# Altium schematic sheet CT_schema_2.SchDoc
size 276 x 169 mm
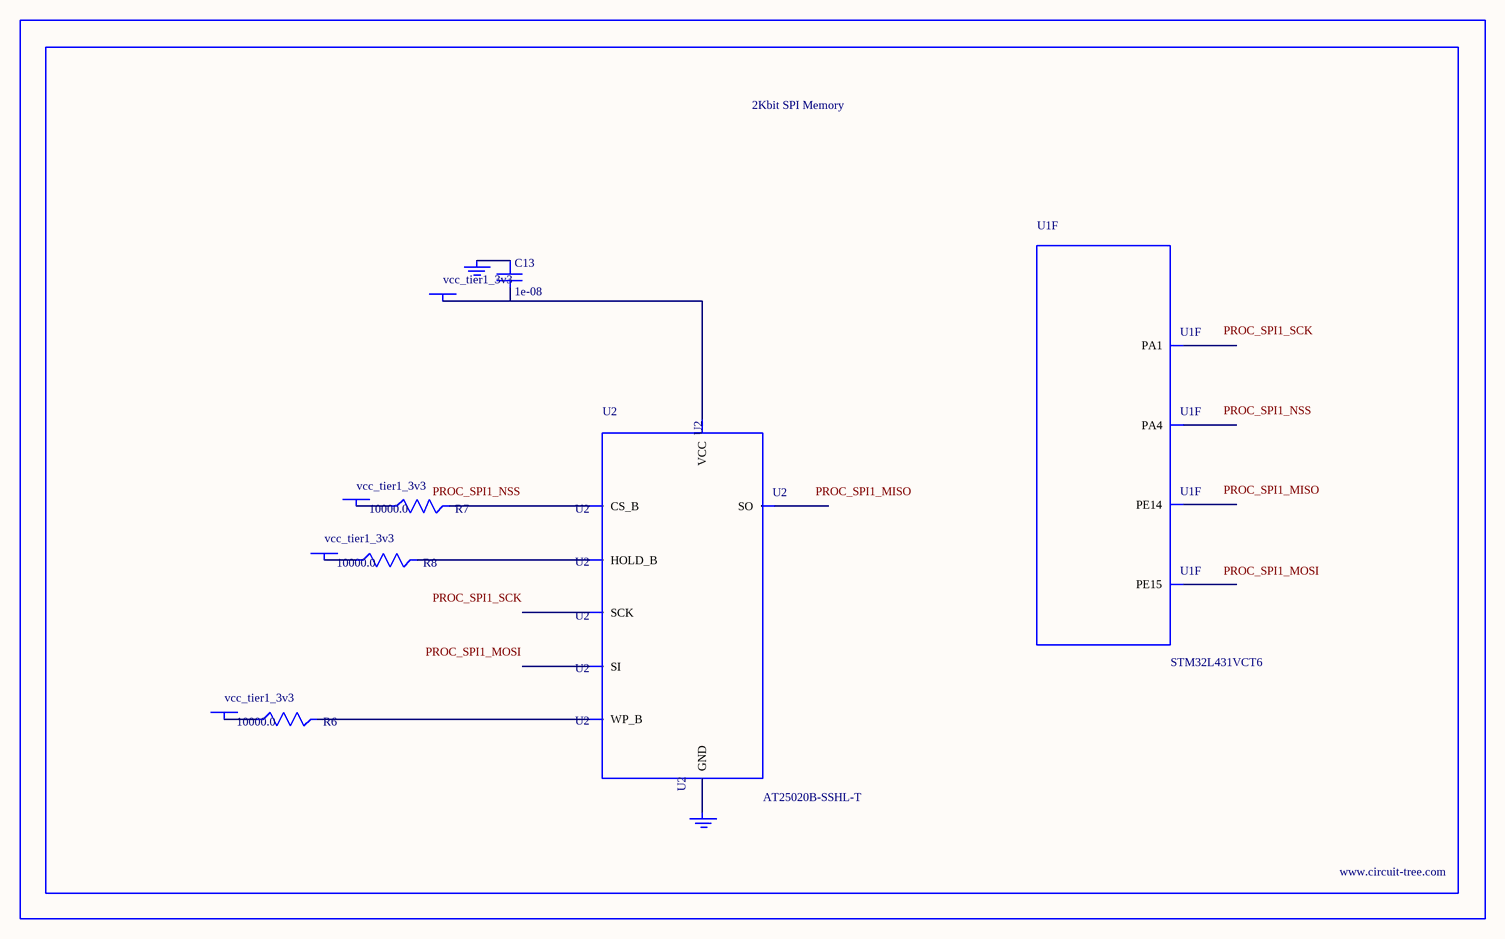
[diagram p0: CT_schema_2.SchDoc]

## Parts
BORDER1  (no value)
C13  1e-08  [C0402]
GND_INSTANCE_1_0  (no value)
GND_INSTANCE_1_1  (no value)
POWER_INSTANCE_1_0  vcc_tier1_3v3
POWER_INSTANCE_1_1  vcc_tier1_3v3
POWER_INSTANCE_1_2  vcc_tier1_3v3
POWER_INSTANCE_1_3  vcc_tier1_3v3
R6  10000.0  [R0603]
R7  10000.0  [R0603]
R8  10000.0  [R0603]
U1  STM32L431VCT6  [LQFP100]  (part F of 8)
U2  AT25020B-SSHL-T  [SOIC-8]

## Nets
NetC13_1: C13.1 GND_INSTANCE_1_0.0(GND)
NetC13_2: C13.2 POWER_INSTANCE_1_3.0(PWR) U2.8(VCC)
NetGND_INSTANCE_1_1_0: GND_INSTANCE_1_1.0(GND) U2.4(GND)
NetPOWER_INSTANCE_1_0_0: POWER_INSTANCE_1_0.0(PWR) R7.1
NetPOWER_INSTANCE_1_1_0: POWER_INSTANCE_1_1.0(PWR) R6.1
NetPOWER_INSTANCE_1_2_0: POWER_INSTANCE_1_2.0(PWR) R8.1
NetR6_2: R6.2 U2.3(WP_B)
NetR7_2: R7.2 U2.1(CS_B)
NetR8_2: R8.2 U2.7(HOLD_B)

Not connected (* = marked no-connect by the designer): U1 24(PA1) 29(PA4) 45(PE14) 46(PE15); U2 2(SO) 5(SI) 6(SCK)

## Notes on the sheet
- Labels drawn without touching a wire or pin: PROC_SPI1_MISO, PROC_SPI1_MOSI, PROC_SPI1_NSS, PROC_SPI1_SCK

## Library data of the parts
BORDER1 = BORDER_PAGE1
C13 = C0402C103K3RAC
GND_INSTANCE_1_0 GND_INSTANCE_1_1 = GND
POWER_INSTANCE_1_0-POWER_INSTANCE_1_3 = PWR
R6-R8 = RC0603JR-0710KL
